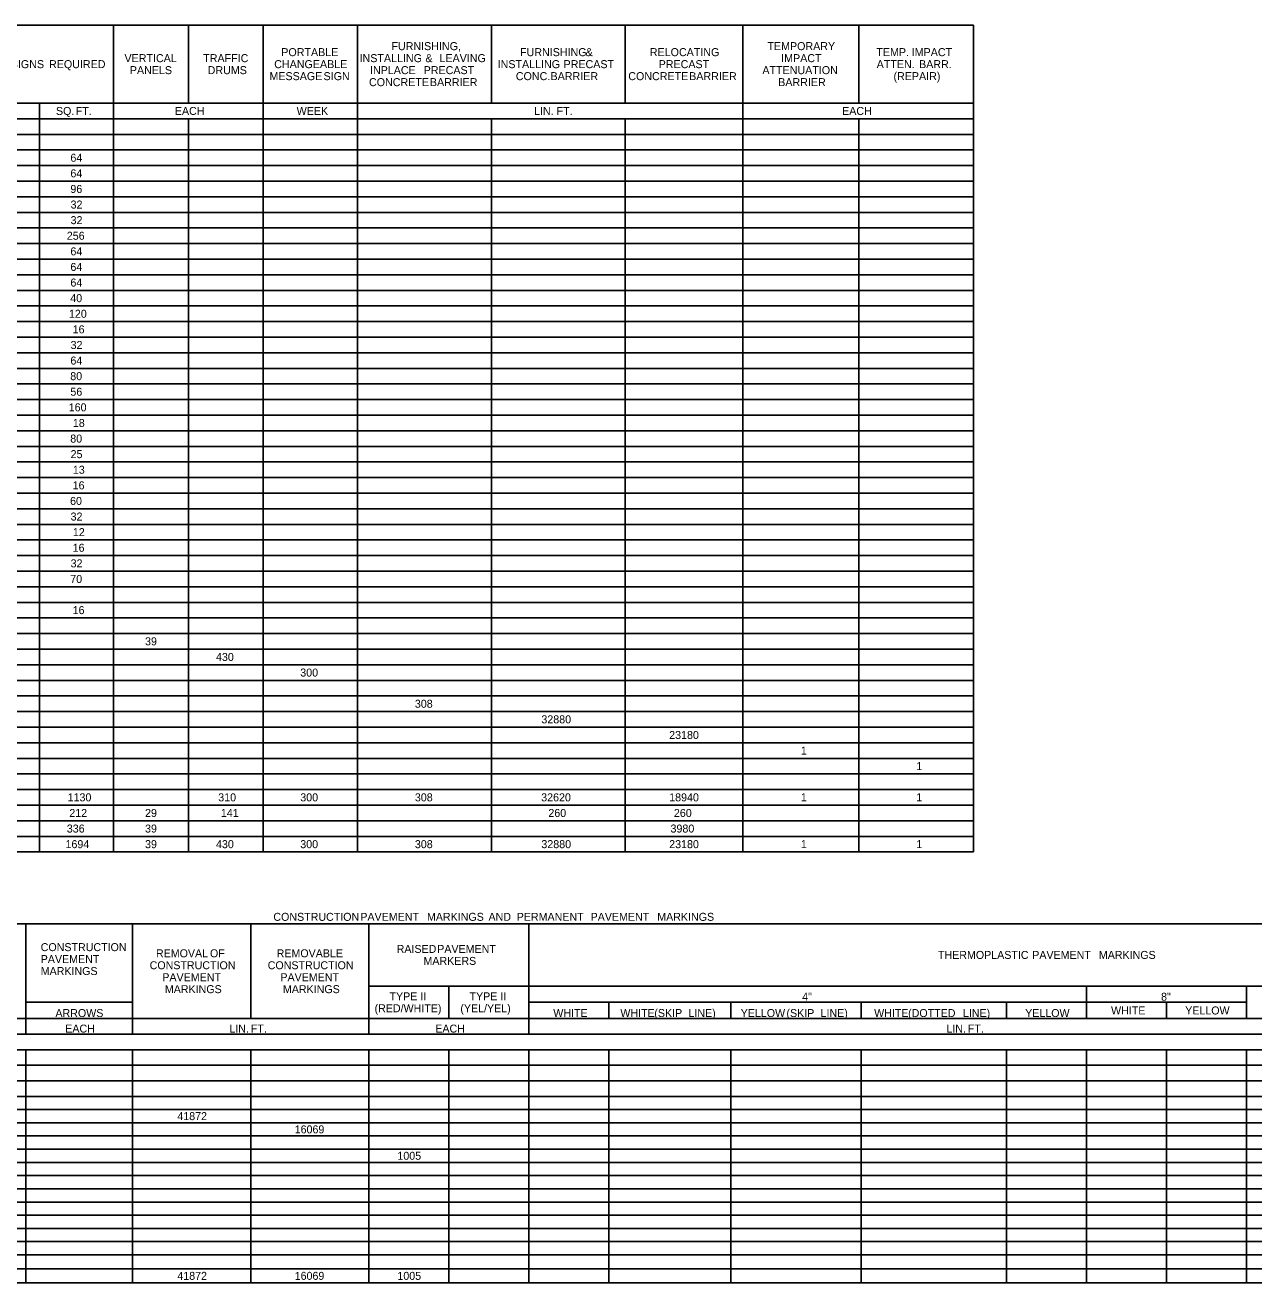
# Model space of a CAD drawing. Extents: x 1225909 to 1228704, y 151309 to 152305.
# Drawn here: x 1227206 to 1227705, y 151769 to 152280 of the extents above; entities that cross this region are included whole.
import ezdxf

# ---------------------------------------------------------------- set-up
doc = ezdxf.new("R2010")
doc.units = 0
doc.layers.add('R_Dimension', color=7, linetype='Continuous')

msp = doc.modelspace()

# ---------------------------------------------------------------- linework, layer by layer
at = {"layer": 'R_Dimension'}
for p, q in [((1226577.42, 152279.62), (1227591.1, 152279.62)), ((1227241.59, 151943.73), (1227241.59, 152279.62)), ((1227272.01, 152247.93), (1227272.01, 152279.62)), ((1227302.43, 151943.73), (1227302.43, 152279.62)), ((1227340.77, 151943.73), (1227340.77, 152279.62)), ((1227395.27, 152247.93), (1227395.27, 152279.62)), ((1227449.46, 152247.93), (1227449.46, 152279.62)), ((1227497.31, 152241.6), (1227497.31, 152279.62)), ((1227544.52, 152247.93), (1227544.52, 152279.62)), ((1227591.1, 151943.73), (1227591.1, 152279.62)), ((1227181.38, 152247.93), (1227591.1, 152247.93)), ((1227211.49, 151943.73), (1227211.49, 152247.93)), ((1226577.42, 152241.6), (1227591.1, 152241.6)), ((1227151.28, 152241.6), (1227591.1, 152241.6)), ((1227272.01, 151943.73), (1227272.01, 152241.6)), ((1227395.27, 151943.73), (1227395.27, 152241.6)), ((1227449.46, 151943.73), (1227449.46, 152241.6)), ((1227497.31, 151943.73), (1227497.31, 152241.6)), ((1227544.52, 151943.73), (1227544.52, 152241.6)), ((1226577.42, 152235.26), (1227591.1, 152235.26)), ((1226577.42, 152228.92), (1227591.1, 152228.92)), ((1226577.42, 152222.58), (1227591.1, 152222.58)), ((1226577.42, 152216.25), (1227591.1, 152216.25)), ((1226577.42, 152209.91), (1227591.1, 152209.91)), ((1226577.42, 152203.57), (1227591.1, 152203.57)), ((1226577.42, 152197.23), (1227591.1, 152197.23)), ((1226577.42, 152190.9), (1227591.1, 152190.9)), ((1226577.42, 152184.56), (1227591.1, 152184.56)), ((1226577.42, 152178.22), (1227591.1, 152178.22)), ((1226577.42, 152171.88), (1227591.1, 152171.88)), ((1226577.42, 152165.55), (1227591.1, 152165.55)), ((1226577.42, 152159.21), (1227591.1, 152159.21)), ((1226577.42, 152152.87), (1227591.1, 152152.87)), ((1226577.42, 152146.53), (1227591.1, 152146.53)), ((1226577.42, 152140.2), (1227591.1, 152140.2)), ((1226577.42, 152133.86), (1227591.1, 152133.86)), ((1226577.42, 152127.52), (1227591.1, 152127.52)), ((1226577.42, 152121.18), (1227591.1, 152121.18)), ((1226577.42, 152114.85), (1227591.1, 152114.85)), ((1226577.42, 152108.51), (1227591.1, 152108.51)), ((1226577.42, 152102.17), (1227591.1, 152102.17)), ((1226577.42, 152095.83), (1227591.1, 152095.83)), ((1226577.42, 152089.5), (1227591.1, 152089.5)), ((1226577.42, 152083.16), (1227591.1, 152083.16)), ((1226577.42, 152076.82), (1227591.1, 152076.82)), ((1226577.42, 152070.48), (1227591.1, 152070.48)), ((1226577.42, 152064.15), (1227591.1, 152064.15)), ((1226577.42, 152057.81), (1227591.1, 152057.81)), ((1226577.42, 152051.47), (1227591.1, 152051.47)), ((1226577.42, 152045.13), (1227591.1, 152045.13)), ((1226577.42, 152038.8), (1227591.1, 152038.8)), ((1226577.42, 152032.46), (1227591.1, 152032.46)), ((1226577.42, 152026.12), (1227591.1, 152026.12)), ((1226577.42, 152019.78), (1227591.1, 152019.78)), ((1226577.42, 152013.45), (1227591.1, 152013.45)), ((1226577.42, 152007.11), (1227591.1, 152007.11)), ((1226577.42, 152000.77), (1227591.1, 152000.77)), ((1226577.42, 151994.43), (1227591.1, 151994.43)), ((1226577.42, 151988.1), (1227591.1, 151988.1)), ((1226577.42, 151981.76), (1227591.1, 151981.76)), ((1226577.42, 151975.42), (1227591.1, 151975.42)), ((1226577.42, 151969.08), (1227591.1, 151969.08)), ((1226577.42, 151962.75), (1227591.1, 151962.75)), ((1226577.42, 151956.41), (1227591.1, 151956.41)), ((1226577.42, 151950.07), (1227591.1, 151950.07)), ((1226577.42, 151943.73), (1227591.1, 151943.73)), ((1226577.42, 151914.54), (1228151.92, 151914.54)), ((1227205.96, 151869.71), (1227205.96, 151914.54)), ((1227249.36, 151869.71), (1227249.36, 151914.54)), ((1227297.35, 151876.02), (1227297.35, 151914.54)), ((1227345.33, 151869.71), (1227345.33, 151914.54)), ((1227410.36, 151869.71), (1227410.36, 151914.54)), ((1227345.33, 151889.28), (1228151.92, 151889.28)), ((1227377.85, 151876.02), (1227377.85, 151889.28)), ((1227637.03, 151876.02), (1227637.03, 151889.28)), ((1227702.06, 151876.02), (1227702.06, 151889.28)), ((1227205.96, 151882.65), (1227249.36, 151882.65)), ((1227410.36, 151882.65), (1227702.06, 151882.65)), ((1227442.88, 151876.02), (1227442.88, 151882.65)), ((1227492.44, 151876.02), (1227492.44, 151882.65)), ((1227545.48, 151876.02), (1227545.48, 151882.65)), ((1227604.51, 151876.02), (1227604.51, 151882.65)), ((1227669.54, 151876.02), (1227669.54, 151882.65)), ((1226750.73, 151876.02), (1228151.92, 151876.02)), ((1227249.36, 151876.02), (1227702.06, 151876.02)), ((1227702.06, 151876.02), (1228151.92, 151876.02)), ((1226577.42, 151869.71), (1228151.92, 151869.71)), ((1226577.42, 151863.4), (1228151.92, 151863.4)), ((1227205.96, 151768.69), (1227205.96, 151863.4)), ((1227249.36, 151768.69), (1227249.36, 151863.4)), ((1227297.35, 151768.69), (1227297.35, 151863.4)), ((1227345.33, 151768.69), (1227345.33, 151863.4)), ((1227377.85, 151768.69), (1227377.85, 151863.4)), ((1227410.36, 151768.69), (1227410.36, 151863.4)), ((1227442.88, 151768.69), (1227442.88, 151863.4)), ((1227492.44, 151768.69), (1227492.44, 151863.4)), ((1227545.48, 151768.69), (1227545.48, 151863.4)), ((1227604.51, 151768.69), (1227604.51, 151863.4)), ((1227637.03, 151768.69), (1227637.03, 151863.4)), ((1227669.54, 151768.69), (1227669.54, 151863.4)), ((1227702.06, 151768.69), (1227702.06, 151863.4)), ((1226577.42, 151857.08), (1228151.92, 151857.08)), ((1226577.42, 151850.77), (1228151.92, 151850.77)), ((1226577.42, 151844.45), (1228151.92, 151844.45)), ((1226577.42, 151839.09), (1228151.92, 151839.09)), ((1226577.42, 151833.72), (1228151.92, 151833.72)), ((1226577.42, 151828.35), (1228151.92, 151828.35)), ((1226577.42, 151822.99), (1228151.92, 151822.99)), ((1226577.42, 151817.62), (1228151.92, 151817.62)), ((1226577.42, 151812.25), (1228151.92, 151812.25)), ((1226577.42, 151806.89), (1228151.92, 151806.89)), ((1226577.42, 151801.52), (1228151.92, 151801.52)), ((1226577.42, 151796.15), (1228151.92, 151796.15)), ((1226577.42, 151790.79), (1228151.92, 151790.79)), ((1226577.42, 151785.42), (1228151.92, 151785.42)), ((1226577.42, 151780.05), (1228151.92, 151780.05)), ((1226577.42, 151774.37), (1228151.92, 151774.37)), ((1226577.42, 151768.69), (1228151.92, 151768.69))]:
    msp.add_line(p, q, dxfattribs=at)

# ---------------------------------------------------------------- texts
for s, height, p in [('PORTABLE', 3.25, (1227309.78, 152267.03)), ('FURNISHING,', 3.25, (1227354.54, 152269.47)), ('FURNISHING', 3.25, (1227406.81, 152267.03)), (' &', 3.25, (1227432.22, 152267.03)), ('RELOCATING', 3.25, (1227459.55, 152267.03)), ('TEMPORARY', 3.25, (1227507.33, 152269.47)), ('TEMP.', 3.25, (1227551.61, 152267.03)), (' IMPACT', 3.25, (1227564.77, 152267.03)), (' SIGNS', 3.25, (1227198.65, 152262.15)), (' REQUIRED', 3.25, (1227214.19, 152262.15)), ('VERTICAL', 3.25, (1227246.05, 152264.59)), ('PANELS', 3.25, (1227248.23, 152259.72)), ('TRAFFIC', 3.25, (1227278.05, 152264.59)), ('DRUMS', 3.25, (1227279.85, 152259.72)), ('CHANGEABLE', 3.25, (1227306.91, 152262.15)), ('INSTALLING', 3.25, (1227341.59, 152264.59)), ('IN', 3.25, (1227345.86, 152259.72)), (' PLACE', 3.25, (1227348.96, 152259.72)), (' PRECAST', 3.25, (1227366.44, 152259.72)), (' &', 3.25, (1227367.15, 152264.59)), (' LEAVING', 3.25, (1227372.86, 152264.59)), ('INSTALLING', 3.25, (1227397.71, 152262.15)), (' PRECAST', 3.25, (1227423.28, 152262.15)), ('PRECAST', 3.25, (1227463.14, 152262.15)), ('ATTENUATION', 3.25, (1227505.29, 152259.72)), ('IMPACT', 3.25, (1227512.92, 152264.59)), ('ATTEN.', 3.25, (1227551.73, 152262.15)), (' BARR.', 3.25, (1227567.75, 152262.15)), ('MESSAGE', 3.25, (1227304.97, 152257.28)), (' SIGN', 3.25, (1227325.75, 152257.28)), ('CONCRETE', 3.25, (1227345.43, 152254.84)), (' BARRIER', 3.25, (1227368.97, 152254.84)), ('CONC.', 3.25, (1227405.09, 152257.28)), (' BARRIER', 3.25, (1227417.99, 152257.28)), ('CONCRETE', 3.25, (1227450.79, 152257.28)), (' BARRIER', 3.25, (1227474.33, 152257.28)), ('BARRIER', 3.25, (1227511.72, 152254.84)), ('(REPAIR)', 3.25, (1227558.57, 152257.28)), ('SQ.', 3.25, (1227218.21, 152243.14)), (' FT.', 3.25, (1227225.02, 152243.14)), ('EACH', 3.25, (1227266.51, 152243.14)), ('WEEK', 3.25, (1227316.02, 152243.14)), ('LIN. FT.', 3.25, (1227412.49, 152243.14)), ('EACH', 3.25, (1227537.68, 152243.14)), ('64', 3.25, (1227224.08, 152224.13)), ('64', 3.25, (1227224.08, 152217.79)), ('96', 3.25, (1227224.07, 152211.45)), ('32', 3.25, (1227224.16, 152205.12)), ('32', 3.25, (1227224.16, 152198.78)), ('256', 3.25, (1227222.61, 152192.44)), ('64', 3.25, (1227224.08, 152186.1)), ('64', 3.25, (1227224.08, 152179.77)), ('64', 3.25, (1227224.08, 152173.43)), ('40', 3.25, (1227224.02, 152167.09)), ('120', 3.25, (1227223.48, 152160.75)), ('16', 3.25, (1227224.99, 152154.42)), ('32', 3.25, (1227224.16, 152148.08)), ('64', 3.25, (1227224.08, 152141.74)), ('80', 3.25, (1227224.02, 152135.4)), ('56', 3.25, (1227224.07, 152129.07)), ('160', 3.25, (1227223.4, 152122.73)), ('18', 3.25, (1227225.08, 152116.39)), ('80', 3.25, (1227224.02, 152110.05)), ('25', 3.25, (1227224.16, 152103.72)), ('13', 3.25, (1227225.08, 152097.38)), ('16', 3.25, (1227224.99, 152091.04)), ('60', 3.25, (1227223.94, 152084.7)), ('32', 3.25, (1227224.16, 152078.37)), ('12', 3.25, (1227225.08, 152072.03)), ('16', 3.25, (1227224.99, 152065.69)), ('32', 3.25, (1227224.16, 152059.35)), ('70', 3.25, (1227224.02, 152053.02)), ('16', 3.25, (1227224.99, 152040.34)), ('39', 3.25, (1227254.41, 152027.67)), ('430', 3.25, (1227283.24, 152021.33)), ('300', 3.25, (1227317.49, 152014.99)), ('308', 3.25, (1227364.06, 152002.32)), ('32880', 3.25, (1227415.47, 151995.98)), ('23180', 3.25, (1227467.41, 151989.64)), ('1', 3.25, (1227520.92, 151983.3)), ('1', 3.25, (1227567.81, 151976.97)), ('1130', 3.25, (1227222.94, 151964.29)), ('310', 3.25, (1227284.16, 151964.29)), ('300', 3.25, (1227317.49, 151964.29)), ('308', 3.25, (1227364.06, 151964.29)), ('32620', 3.25, (1227415.39, 151964.29)), ('18940', 3.25, (1227467.41, 151964.29)), ('1', 3.25, (1227520.92, 151964.29)), ('1', 3.25, (1227567.81, 151964.29)), ('212', 3.25, (1227223.62, 151957.95)), ('29', 3.25, (1227254.41, 151957.95)), ('141', 3.25, (1227285.22, 151957.95)), ('260', 3.25, (1227418.31, 151957.95)), ('260', 3.25, (1227469.33, 151957.95)), ('336', 3.25, (1227222.61, 151951.62)), ('39', 3.25, (1227254.41, 151951.62)), ('3980', 3.25, (1227467.95, 151951.62)), ('1694', 3.25, (1227222.09, 151945.28)), ('39', 3.25, (1227254.41, 151945.28)), ('430', 3.25, (1227283.24, 151945.28)), ('300', 3.25, (1227317.49, 151945.28)), ('308', 3.25, (1227364.06, 151945.28)), ('32880', 3.25, (1227415.47, 151945.28)), ('23180', 3.25, (1227467.41, 151945.28)), ('1', 3.25, (1227520.92, 151945.28)), ('1', 3.25, (1227567.81, 151945.28)), ('CONSTRUCTION', 3.2378, (1227306.57, 151915.76)), (' PAVEMENT', 3.238, (1227340.7, 151915.76)), (' MARKINGS', 3.238, (1227367.78, 151915.76)), (' AND', 3.238, (1227392.79, 151915.76)), (' PERMANENT', 3.238, (1227404.26, 151915.76)), (' PAVEMENT', 3.238, (1227434.29, 151915.76)), (' MARKINGS', 3.238, (1227461.37, 151915.76)), ('CONSTRUCTION ', 3.2378, (1227212.02, 151903.45)), ('RAISED', 3.238, (1227356.67, 151902.72)), (' PAVEMENT', 3.238, (1227371.95, 151902.72)), ('PAVEMENT', 3.238, (1227212.02, 151898.6)), ('REMOVAL', 3.238, (1227258.85, 151900.95)), (' OF', 3.238, (1227279.6, 151900.95)), ('REMOVABLE', 3.238, (1227307.9, 151900.95)), ('MARKERS', 3.238, (1227367.57, 151897.86)), ('THERMOPLASTIC', 3.2378, (1227576.65, 151900.29)), (' PAVEMENT', 3.238, (1227613.75, 151900.29)), (' MARKINGS', 3.238, (1227640.82, 151900.29)), ('MARKINGS', 3.238, (1227212.02, 151893.74)), ('CONSTRUCTION', 3.2378, (1227256.29, 151896.09)), ('CONSTRUCTION', 3.2378, (1227304.27, 151896.09)), ('PAVEMENT', 3.238, (1227261.44, 151891.23)), ('PAVEMENT', 3.238, (1227309.42, 151891.23)), ('MARKINGS', 3.238, (1227262.47, 151886.38)), ('MARKINGS', 3.238, (1227310.45, 151886.38)), ('TYPE', 3.238, (1227353.77, 151883.46)), (' II', 3.238, (1227365.09, 151883.46)), ('TYPE', 3.238, (1227386.29, 151883.46)), (' II', 3.238, (1227397.61, 151883.46)), ('4"', 3.238, (1227521.46, 151883.3)), ('8"', 3.238, (1227667.31, 151883.3)), ('ARROWS', 3.238, (1227218, 151876.67)), ('(RED/WHITE)', 3.2378, (1227347.69, 151878.61)), ('(YEL/YEL)', 3.238, (1227382.56, 151878.61)), ('WHITE', 3.238, (1227420.32, 151876.67)), ('WHITE', 3.238, (1227447.58, 151876.67)), (' (SKIP', 3.238, (1227460.18, 151876.67)), (' LINE)', 3.238, (1227474.05, 151876.67)), ('YELLOW', 3.238, (1227496.49, 151876.67)), (' (SKIP', 3.238, (1227513.87, 151876.67)), (' LINE)', 3.238, (1227527.74, 151876.67)), ('WHITE', 3.238, (1227550.71, 151876.67)), (' (DOTTED', 3.238, (1227563.31, 151876.67)), (' LINE)', 3.238, (1227585.59, 151876.67)), ('YELLOW', 3.238, (1227612.08, 151876.67)), ('WHITE', 3.238, (1227646.99, 151877.72)), ('YELLOW', 3.238, (1227677.11, 151877.72)), ('EACH', 3.238, (1227221.99, 151870.36)), ('LIN.', 3.238, (1227288.67, 151870.36)), (' FT.', 3.238, (1227296.21, 151870.36)), ('EACH', 3.238, (1227372.37, 151870.36)), ('LIN.', 3.238, (1227580.05, 151870.36)), (' FT.', 3.238, (1227587.59, 151870.36)), ('41872', 3.238, (1227267.54, 151834.79)), ('16069', 3.238, (1227315.23, 151829.42)), ('1005', 3.238, (1227356.97, 151818.69)), ('41872', 3.238, (1227267.54, 151769.91)), ('16069', 3.238, (1227315.23, 151769.91)), ('1005', 3.238, (1227356.97, 151769.91))]:
    msp.add_text(s, height=height, dxfattribs=at).set_placement(p)

doc.saveas('drawing.dxf')
